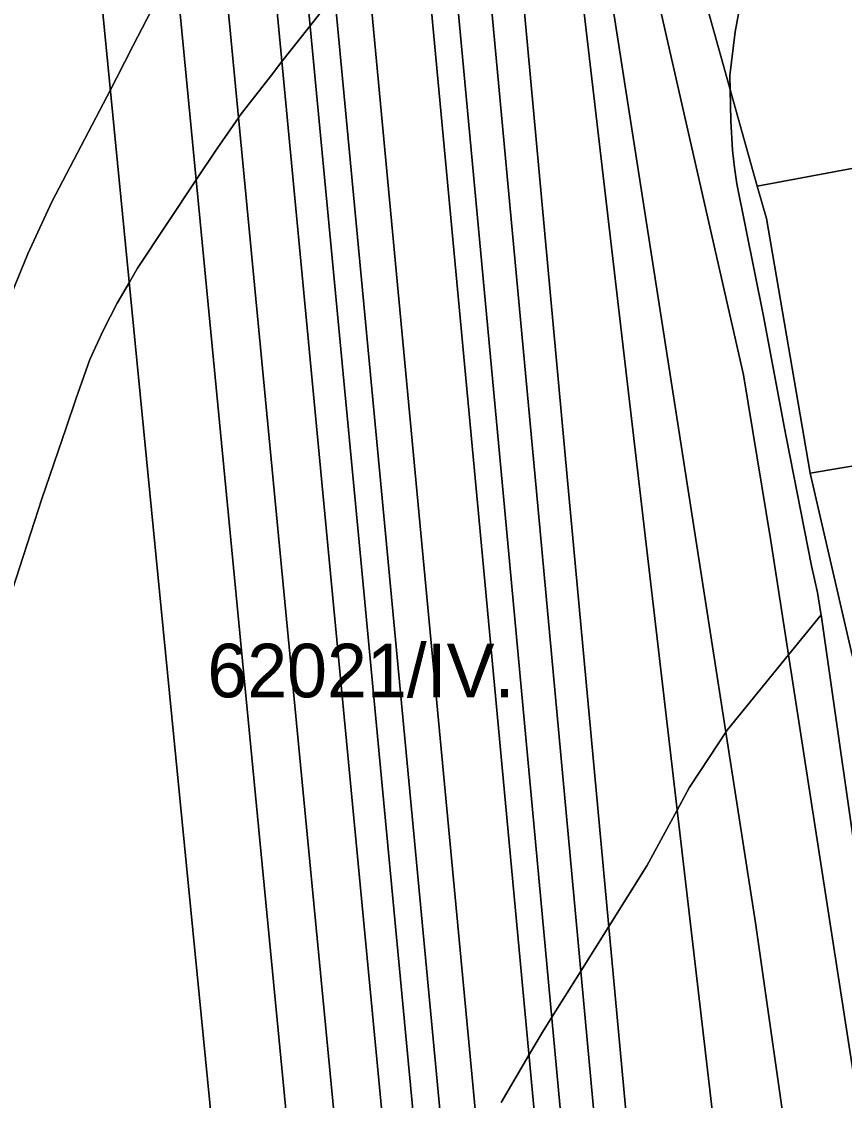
# Model space of a CAD drawing. Extents: x -521939 to -516426, y -1197857 to -1189551.
# Drawn here: x -518713.5 to -518483.4, y -1191708.6 to -1191406.6 of the extents above; entities that cross this region are included whole.
import ezdxf

# ---------------------------------------------------------------- set-up
doc = ezdxf.new("R2010")
doc.units = 0
for name, color, linetype in [('95560013', 7, 'Continuous'), ('95610013', 7, 'Continuous'), ('95640013', 7, 'Continuous'), ('95660013', 7, 'Continuous')]:
    doc.layers.add(name, color=color, linetype=linetype)

msp = doc.modelspace()

# ---------------------------------------------------------------- linework, layer by layer
at = {"layer": '95560013'}
for points in [[(-518556.44, -1191349.16), (-518528.88, -1191526.36), (-518508.28, -1191658.81), (-518483.09, -1191835.12), (-518458.07, -1192010.24), (-518487.38, -1191994.82), (-518498.99, -1191895.13), (-518520.13, -1191713.61), (-518541.27, -1191532.09), (-518562.41, -1191350.57)], [(-518550.53, -1191347.83), (-518534.55, -1191404.6), (-518511.67, -1191505.47), (-518504.02, -1191551.95), (-518475.27, -1191737.43), (-518456.08, -1191919), (-518442.18, -1192018.62), (-518458.07, -1192010.24), (-518483.09, -1191835.12), (-518508.28, -1191658.81), (-518528.88, -1191526.36), (-518556.44, -1191349.16)], [(-518562.41, -1191350.57), (-518541.27, -1191532.09), (-518520.13, -1191713.61), (-518498.99, -1191895.13), (-518487.38, -1191994.82), (-518520.08, -1191977.58), (-518527.65, -1191895.33), (-518544.2, -1191715.51), (-518560.9, -1191534.06), (-518577.45, -1191354.24)], [(-518577.45, -1191354.24), (-518560.9, -1191534.06), (-518544.2, -1191715.51), (-518527.65, -1191895.33), (-518520.08, -1191977.58), (-518529.34, -1191972.72), (-518536.24, -1191898.15), (-518552.74, -1191719.83), (-518569.55, -1191538.16), (-518586.36, -1191356.49), (-518585.03, -1191356.06)], [(-518586.36, -1191356.49), (-518569.55, -1191538.16), (-518552.74, -1191719.83), (-518536.24, -1191898.15), (-518529.34, -1191972.72), (-518538.97, -1191967.67), (-518545.26, -1191900.03), (-518562.02, -1191719.8), (-518578.78, -1191539.57), (-518595.54, -1191359.34)], [(-518601.86, -1191549.79), (-518619.05, -1191366.96), (-518611.69, -1191364.61), (-518602.82, -1191361.7), (-518586.34, -1191538.31), (-518553.38, -1191891.53), (-518546.64, -1191963.76), (-518555.88, -1191959.88), (-518563.58, -1191956.93), (-518567.15, -1191918.96), (-518584.56, -1191733.79)], [(-518553.38, -1191891.53), (-518586.34, -1191538.31), (-518602.82, -1191361.7), (-518595.54, -1191359.34), (-518578.78, -1191539.57), (-518562.02, -1191719.8), (-518545.26, -1191900.03), (-518538.97, -1191967.67), (-518546.64, -1191963.76)], [(-518573.63, -1191953.32), (-518577.55, -1191911.83), (-518594.65, -1191730.84), (-518611.75, -1191549.85), (-518628.73, -1191370.13), (-518619.05, -1191366.96), (-518601.86, -1191549.79), (-518584.56, -1191733.79), (-518567.15, -1191918.96), (-518563.58, -1191956.93)], [(-518628.73, -1191370.13), (-518611.75, -1191549.85), (-518594.65, -1191730.84), (-518577.55, -1191911.83), (-518573.63, -1191953.32), (-518581.33, -1191951.39), (-518585, -1191912.66), (-518602.03, -1191732.94), (-518619.15, -1191552.27), (-518636.18, -1191372.55)], [(-518636.18, -1191372.55), (-518619.15, -1191552.27), (-518602.03, -1191732.94), (-518585, -1191912.66), (-518581.33, -1191951.39), (-518590.16, -1191949.07), (-518592.82, -1191921.12), (-518610.14, -1191739.13), (-518627.46, -1191557.14), (-518644.76, -1191375.36)], [(-518644.76, -1191375.36), (-518627.46, -1191557.14), (-518610.14, -1191739.13), (-518592.82, -1191921.12), (-518590.16, -1191949.07), (-518603.83, -1191945.37), (-518606.97, -1191912.58), (-518623.98, -1191734.95), (-518640.99, -1191557.32), (-518658, -1191379.69)], [(-518658, -1191379.69), (-518640.99, -1191557.32), (-518623.98, -1191734.95), (-518606.97, -1191912.58), (-518603.83, -1191945.37), (-518617.37, -1191941.7), (-518636.53, -1191743.04), (-518652, -1191582.64), (-518671.16, -1191383.98)], [(-518671.16, -1191383.98), (-518652, -1191582.64), (-518636.53, -1191743.04), (-518617.37, -1191941.7), (-518638.68, -1191935.9), (-518656.8, -1191750.93), (-518674.44, -1191570.86), (-518692.08, -1191390.79)], [(-518692.08, -1191390.79), (-518674.44, -1191570.86), (-518656.8, -1191750.93), (-518638.68, -1191935.9), (-518720.06, -1191913.74), (-518725.58, -1191845.32), (-518740.24, -1191663.61), (-518754.85, -1191482.52), (-518745.17, -1191421.89), (-518741.69, -1191406.71), (-518737.43, -1191406.49), (-518728.9, -1191402.78)]]:
    msp.add_lwpolyline(points, close=True, dxfattribs=at)
at = {"layer": '95610013'}
for points in [[(-518439.4, -1191439.86), (-518507.78, -1191452.68), (-518523.95, -1191394.84), (-518457.15, -1191381.15), (-518443.9, -1191423.5)], [(-518421.64, -1191520.99), (-518492.98, -1191533.04), (-518505.21, -1191461.73), (-518507.78, -1191452.68), (-518439.4, -1191439.86)], [(-518410.47, -1191583.23), (-518477.36, -1191595.24), (-518481.26, -1191583.91), (-518492.98, -1191533.04), (-518421.64, -1191520.99), (-518418.21, -1191537.31)]]:
    msp.add_lwpolyline(points, close=True, dxfattribs=at)
at = {"layer": '95640013'}
msp.add_lwpolyline([(-518507.78, -1191452.68), (-518505.21, -1191461.73), (-518492.98, -1191533.04), (-518481.26, -1191583.91), (-518477.36, -1191595.24), (-518479.16, -1191647.79), (-518473.02, -1191676.18), (-518469.66, -1191697.37), (-518466.4, -1191722.26), (-518464.87, -1191741.35), (-518454.59, -1191853.4), (-518450.7, -1191900.44), (-518448.71, -1191923.59), (-518432.53, -1192000.31), (-518426.98, -1192026.71), (-518442.18, -1192018.62), (-518456.08, -1191919), (-518475.27, -1191737.43), (-518504.02, -1191551.95), (-518511.67, -1191505.47), (-518534.55, -1191404.6), (-518550.53, -1191347.83), (-518539.79, -1191345.38), (-518523.95, -1191394.84)], close=True, dxfattribs=at)
at = {"layer": '95660013'}
for points in [[(-518510.95, -1191393.23), (-518513.96, -1191409.46), (-518515.41, -1191421.7), (-518515.34, -1191425.64), (-518515.18, -1191434.37), (-518514.71, -1191442.59), (-518514.1, -1191447.48), (-518513.53, -1191451.98), (-518506.02, -1191489.07), (-518500.26, -1191519.89), (-518499.62, -1191523.28), (-518492.58, -1191558.91), (-518490.94, -1191566.42), (-518490, -1191572.29), (-518489.95, -1191572.63), (-518499.07, -1191583.86), (-518516.16, -1191604.89), (-518516.57, -1191605.51), (-518521.06, -1191612.34), (-518526.83, -1191621.11), (-518530.18, -1191627.29), (-518538.65, -1191642.9), (-518549.32, -1191659.92), (-518557.13, -1191672.38), (-518565.23, -1191685.3), (-518567.86, -1191689.5), (-518571.63, -1191695.92), (-518579.39, -1191709.13)], [(-518479.15, -1191647.6), (-518485.3, -1191604.68), (-518489.95, -1191572.63), (-518490, -1191572.29), (-518490.94, -1191566.42), (-518492.58, -1191558.91), (-518499.62, -1191523.28), (-518500.26, -1191519.89), (-518506.02, -1191489.07), (-518513.53, -1191451.98), (-518514.1, -1191447.48), (-518514.71, -1191442.59), (-518515.18, -1191434.37), (-518515.34, -1191425.64), (-518515.41, -1191421.7), (-518513.96, -1191409.46), (-518510.95, -1191393.23)], [(-518626, -1191398.98), (-518632.84, -1191407.76), (-518633.58, -1191408.71), (-518640.72, -1191417.82), (-518643.66, -1191421.57), (-518652.36, -1191432.82), (-518652.85, -1191433.51), (-518658.85, -1191442.09), (-518664.71, -1191450.91), (-518681.1, -1191475.59), (-518683.38, -1191479.55), (-518686.78, -1191485.44), (-518690.72, -1191493.09), (-518694.43, -1191501.2), (-518698.37, -1191512.33), (-518701.09, -1191520.29), (-518707.88, -1191540.15), (-518718.08, -1191571.91)], [(-518718.08, -1191571.91), (-518707.88, -1191540.15), (-518701.09, -1191520.29), (-518698.37, -1191512.33), (-518694.43, -1191501.2), (-518690.72, -1191493.09), (-518686.78, -1191485.44), (-518683.38, -1191479.55), (-518681.1, -1191475.59), (-518664.71, -1191450.91), (-518658.85, -1191442.09), (-518652.85, -1191433.51), (-518652.36, -1191432.82), (-518643.66, -1191421.57), (-518640.72, -1191417.82), (-518633.58, -1191408.71), (-518632.84, -1191407.76), (-518626, -1191398.98)], [(-518718.05, -1191486.92), (-518711.79, -1191471.62), (-518705.07, -1191457.01), (-518688.66, -1191425.66), (-518686.99, -1191422.47), (-518682.27, -1191413.29), (-518675.97, -1191401.03)], [(-518675.97, -1191401.03), (-518682.27, -1191413.29), (-518686.99, -1191422.47), (-518688.66, -1191425.66), (-518705.07, -1191457.01), (-518711.79, -1191471.62), (-518718.05, -1191486.92)], [(-518579.39, -1191709.13), (-518571.63, -1191695.92), (-518567.86, -1191689.5), (-518565.23, -1191685.3), (-518557.13, -1191672.38), (-518549.32, -1191659.92), (-518538.65, -1191642.9), (-518530.18, -1191627.29), (-518526.83, -1191621.11), (-518521.06, -1191612.34), (-518516.57, -1191605.51), (-518516.16, -1191604.89), (-518499.07, -1191583.86), (-518489.95, -1191572.63), (-518485.3, -1191604.68), (-518479.15, -1191647.6)]]:
    msp.add_lwpolyline(points, dxfattribs=at)

# ---------------------------------------------------------------- texts
msp.add_text('62021/IV.', height=15, rotation=0, dxfattribs=at).set_placement((-518661.57, -1191595.74))

doc.saveas('drawing.dxf')
